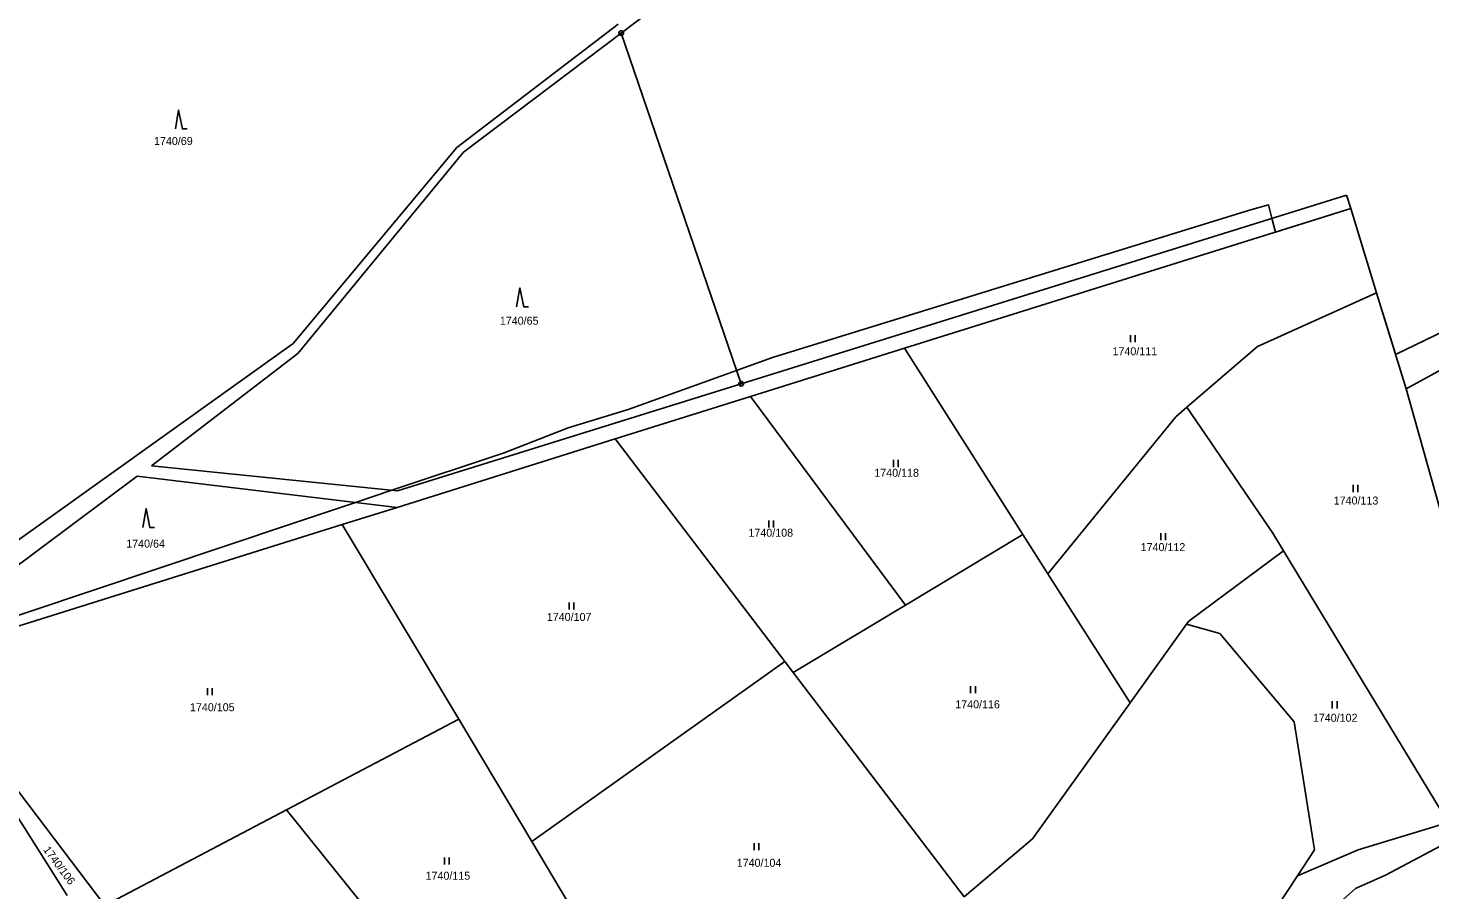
# Model space of a CAD drawing. Extents: x -445050 to -440454, y -1134563 to -1129741.
# Drawn here: x -443735.4 to -443437.5, y -1133430.3 to -1133247.2 of the extents above; entities that cross this region are included whole.
import ezdxf

# ---------------------------------------------------------------- set-up
doc = ezdxf.new("R2010")
doc.units = 0
for name, color, linetype in [('Vrstva 1', 7, 'Continuous'), ('Vrstva 18', 7, 'Continuous'), ('Vrstva 24', 7, 'Continuous'), ('Vrstva 25', 7, 'Continuous'), ('Vrstva 52', 7, 'Continuous'), ('Vrstva 6', 7, 'Continuous')]:
    doc.layers.add(name, color=color, linetype=linetype)

msp = doc.modelspace()

# ---------------------------------------------------------------- linework, layer by layer
at = {"layer": 'Vrstva 1'}
for points in [[(-443609.38, -1133248.28), (-443547.29, -1133201.36)], [(-443610.04, -1133246.38), (-443644.31, -1133272.55)], [(-443642.9, -1133273.6), (-443609.38, -1133248.28)], [(-443609.38, -1133248.28), (-443583.89, -1133322.76)], [(-443644.31, -1133272.55), (-443679.1, -1133314.19)], [(-443678.11, -1133316.31), (-443642.9, -1133273.6)], [(-443455.26, -1133282.67), (-443583.89, -1133322.76)], [(-443454.38, -1133285.54), (-443455.26, -1133282.67)], [(-443549.17, -1133315.23), (-443454.38, -1133285.54)], [(-443448.87, -1133303.46), (-443454.38, -1133285.54)], [(-443388.73, -1133294.37), (-443442.62, -1133323.82)], [(-443442.62, -1133323.82), (-443448.87, -1133303.46)], [(-443679.1, -1133314.19), (-443760.13, -1133372.15)], [(-443709.18, -1133340.18), (-443678.11, -1133316.31)], [(-443581.87, -1133325.47), (-443549.17, -1133315.23)], [(-443583.89, -1133322.76), (-443656.87, -1133345.5)], [(-443610.67, -1133334.49), (-443581.87, -1133325.47)], [(-443418, -1133411.24), (-443442.62, -1133323.82)], [(-443657, -1133349.01), (-443610.67, -1133334.49)], [(-443656.87, -1133345.5), (-443709.18, -1133340.18)], [(-443768.34, -1133384.27), (-443712.18, -1133342.42)], [(-443712.18, -1133342.42), (-443657, -1133349.01)], [(-443668.67, -1133352.67), (-443657, -1133349.01)], [(-443756.74, -1133380.26), (-443668.67, -1133352.67)], [(-443758.95, -1133381.02), (-443727.09, -1133431.44)]]:
    msp.add_lwpolyline(points, dxfattribs=at)
at = {"layer": 'Vrstva 24'}
for centre, radius in [((-443609.38, -1133248.28), 0.5), ((-443609.38, -1133248.28), 0.1), ((-443583.89, -1133322.76), 0.5), ((-443583.89, -1133322.76), 0.1)]:
    msp.add_circle(centre, radius, dxfattribs=at)
at = {"layer": 'Vrstva 25'}
for p, q in [((-443501.16, -1133313.94), (-443501.16, -1133312.44)), ((-443500.16, -1133313.94), (-443500.16, -1133312.44)), ((-443551.51, -1133340.45), (-443551.51, -1133338.95)), ((-443550.51, -1133340.45), (-443550.51, -1133338.95)), ((-443453.84, -1133345.76), (-443453.84, -1133344.26)), ((-443452.84, -1133345.76), (-443452.84, -1133344.26)), ((-443578.01, -1133353.32), (-443578.01, -1133351.82)), ((-443577.01, -1133353.32), (-443577.01, -1133351.82)), ((-443494.72, -1133355.98), (-443494.72, -1133354.48)), ((-443493.72, -1133355.98), (-443493.72, -1133354.48)), ((-443620.41, -1133370.74), (-443620.41, -1133369.24)), ((-443619.41, -1133370.74), (-443619.41, -1133369.24)), ((-443697.26, -1133388.92), (-443697.26, -1133387.42)), ((-443696.26, -1133388.92), (-443696.26, -1133387.42)), ((-443535.13, -1133388.49), (-443535.13, -1133386.99)), ((-443534.13, -1133388.49), (-443534.13, -1133386.99)), ((-443458.29, -1133391.7), (-443458.29, -1133390.2)), ((-443457.29, -1133391.7), (-443457.29, -1133390.2)), ((-443581.15, -1133421.82), (-443581.15, -1133420.32)), ((-443580.15, -1133421.82), (-443580.15, -1133420.32)), ((-443646.91, -1133424.89), (-443646.91, -1133423.39)), ((-443645.91, -1133424.89), (-443645.91, -1133423.39))]:
    msp.add_line(p, q, dxfattribs=at)
for points in [[(-443704.1, -1133268.64), (-443703.4, -1133264.64), (-443702.6, -1133268.64), (-443701.6, -1133268.64)], [(-443631.59, -1133306.41), (-443630.89, -1133302.41), (-443630.09, -1133306.41), (-443629.09, -1133306.41)], [(-443711.03, -1133353.28), (-443710.33, -1133349.28), (-443709.53, -1133353.28), (-443708.53, -1133353.28)]]:
    msp.add_lwpolyline(points, dxfattribs=at)
at = {"layer": 'Vrstva 52'}
for points in [[(-443763.4, -1133380.59), (-443679.42, -1133352.48), (-443665.85, -1133347.95), (-443658.12, -1133345.37), (-443634.27, -1133337.41), (-443620.65, -1133332.09), (-443607.88, -1133328.26), (-443584.85, -1133319.94), (-443577.23, -1133317.19), (-443475.91, -1133285.9), (-443471.85, -1133284.74), (-443471.11, -1133287.61)], [(-443471.11, -1133287.61), (-443470.35, -1133290.54), (-443454.38, -1133285.54), (-443448.87, -1133303.46), (-443444.97, -1133316.17), (-443444.85, -1133316.56), (-443430.35, -1133309.52), (-443407.36, -1133297.39), (-443403, -1133295.39), (-443401.63, -1133301.42), (-443381.63, -1133388.88), (-443404.19, -1133403.1)], [(-443462.71, -1133438.31), (-443453.34, -1133430), (-443446.98, -1133427.12), (-443431.76, -1133419.09)]]:
    msp.add_lwpolyline(points, dxfattribs=at)
at = {"layer": 'Vrstva 6'}
for points in [[(-443474.18, -1133314.85), (-443448.87, -1133303.46)], [(-443549.17, -1133315.23), (-443524.01, -1133354.8)], [(-443489.17, -1133327.71), (-443474.18, -1133314.85)], [(-443581.87, -1133325.47), (-443548.99, -1133369.77)], [(-443491.56, -1133329.76), (-443489.17, -1133327.71)], [(-443470.93, -1133354.48), (-443489.17, -1133327.71)], [(-443518.7, -1133363.15), (-443491.56, -1133329.76)], [(-443610.67, -1133334.49), (-443574.63, -1133381.75)], [(-443668.67, -1133352.67), (-443643.85, -1133393.98)], [(-443524.01, -1133354.8), (-443548.99, -1133369.77)], [(-443524.01, -1133354.8), (-443518.7, -1133363.15)], [(-443468.65, -1133358.24), (-443470.93, -1133354.48)], [(-443468.65, -1133358.24), (-443488.79, -1133373.16)], [(-443433.66, -1133415.96), (-443468.65, -1133358.24)], [(-443518.7, -1133363.15), (-443501.27, -1133390.55)], [(-443548.99, -1133369.77), (-443572.86, -1133384.07)], [(-443488.79, -1133373.16), (-443489.27, -1133373.82)], [(-443489.27, -1133373.82), (-443501.27, -1133390.55)], [(-443482.18, -1133375.78), (-443489.27, -1133373.82)], [(-443466.38, -1133394.54), (-443482.18, -1133375.78)], [(-443719.09, -1133433.56), (-443758.95, -1133381.02)], [(-443574.63, -1133381.75), (-443628.38, -1133419.95)], [(-443574.63, -1133381.75), (-443572.86, -1133384.07)], [(-443572.86, -1133384.07), (-443536.53, -1133431.72)], [(-443501.27, -1133390.55), (-443521.99, -1133419.43)], [(-443680.49, -1133413.26), (-443643.85, -1133393.98)], [(-443643.85, -1133393.98), (-443628.38, -1133419.95)], [(-443462.09, -1133421.78), (-443466.38, -1133394.54)], [(-443719.09, -1133433.56), (-443680.49, -1133413.26)], [(-443680.49, -1133413.26), (-443645.84, -1133456.28)], [(-443433.66, -1133415.96), (-443452.8, -1133421.73)], [(-443628.38, -1133419.95), (-443620.56, -1133433.08)], [(-443521.99, -1133419.43), (-443536.53, -1133431.72)], [(-443452.8, -1133421.73), (-443465.7, -1133427.26)], [(-443465.7, -1133427.26), (-443462.09, -1133421.78)], [(-443473.92, -1133439.73), (-443465.7, -1133427.26)]]:
    msp.add_lwpolyline(points, dxfattribs=at)

# ---------------------------------------------------------------- texts
at = {"layer": 'Vrstva 18'}
for s, p in [('1740/69', (-443708.63, -1133272.05)), ('1740/65', (-443635.16, -1133310.22)), ('1740/111', (-443504.99, -1133316.71)), ('1740/118', (-443555.6, -1133342.52)), ('1740/113', (-443458, -1133348.41)), ('1740/64', (-443714.54, -1133357.57)), ('1740/108', (-443582.34, -1133355.25)), ('1740/112', (-443499.01, -1133358.31)), ('1740/107', (-443625.18, -1133373.14)), ('1740/105', (-443700.99, -1133392.31)), ('1740/116', (-443538.4, -1133391.7)), ('1740/102', (-443462.42, -1133394.55)), ('1740/104', (-443584.83, -1133425.35)), ('1740/115', (-443650.94, -1133428.1))]:
    msp.add_text(s, height=1.7, dxfattribs=at).set_placement(p)
msp.add_text('1740/106', height=1.7, rotation=306.7182, dxfattribs=at).set_placement((-443732.26, -1133421.76))

doc.saveas('drawing.dxf')
